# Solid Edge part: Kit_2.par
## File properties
Sűrűség: 0,000 kg/m^3
Pontosság: 0,990
Author: ahadarics
Last saved by: psaghy
Revision: 77
Username: ahadarics
Dokumentum tartalom típus: 0
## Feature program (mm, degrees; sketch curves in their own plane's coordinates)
base feature "unnamed BaseFeature 1"
sketch for "Furat_1" plane through (0, 0, -117) normal (0, 0, -1) x-axis (0, 1, 0)
  hole centre (-23.25, 23.25) bore radius 3.3235
hole "Furat_1" nominal diameter 8 finite  VBottomAngle = 118 deg; ThreadDepth = 16 mm
sketch for "unnamed Hole 1" plane through (0, 0, -117) normal (0, 0, -1) x-axis (0, 1, 0)
  hole centre (-23.25, -23.25) bore radius 3.3235
hole "unnamed Hole 1" finite
sketch for "unnamed Hole 2" plane through (0, 0, -117) normal (0, 0, -1) x-axis (0, 1, 0)
  hole centre (23.25, -23.25) bore radius 3.3235
hole "unnamed Hole 2" finite
sketch for "unnamed Hole 3" plane through (0, 0, -117) normal (0, 0, -1) x-axis (0, 1, 0)
  hole centre (23.25, 23.25) bore radius 3.3235
hole "unnamed Hole 3" finite
pattern "unnamed Pattern 1" of "Furat_1", "unnamed Hole 1", "unnamed Hole 2", "unnamed Hole 3"
sketch for "Furat_5" plane through (32.5, -0.007, -99.2488) normal (1, 0, 0) x-axis (0, 0, -1)
hole "Furat_5" diameter 13.157 finite  ThreadDepth = 10 mm
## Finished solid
Body 1: solid body, 381 faces, 916 edges, 586 vertices, 4 internal voids.
  Faces by surface: plane 155, cylinder 116, torus 41, cone 34, spline 19, swept 9, sphere 7
  Edges by curve: line 399, circle 264, curve on surface 230, spline 23
Bounding box of the edges (mm; curved faces can reach further): 65.001 x 65.000 x 35.000, from (-32.5, -32.5, -121) to (32.5008, 32.5, -86).
Cylindrical faces by radius (mm): R0.3125 x1, R0.3838 x1, R0.4089 x1, R0.4253 x1, R0.4408 x1, R0.5 x7, R0.5003 x1, R0.5483 x1, R0.5961 x1, R0.615 x1, R0.6311 x1, R0.6362 x1, R0.652 x1, R0.6792 x1, R0.73 x1, R0.7378 x1, R0.9114 x1, R0.9398 x1, R1 x12, R1.0011 x6, R1.0026 x1, R1.0394 x1, R1.0539 x1, R1.0734 x1, R1.0987 x1, R1.1871 x1, R1.2561 x1, R1.2722 x2, R1.3621 x1, R1.3711 x1, R1.5 x3, R1.7143 x1, R1.75 x3, R3 x3, R3.3235 x8, R4 x4, R4.15 x4, R4.95 x1, R5 x2, R5.7225 x1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
Conical faces (half-angle, radius in mm at the cone's reference point): 30 deg R5.1443 x1, 31.4296 deg R28.625 x4, 45 deg R2.25 x3, 45 deg R2.5 x3, 45 deg R2.75 x1, 45 deg R2.825 x1, 45 deg R4.3 x8, 45 deg R6.35 x8, 45 deg R6.72 x1, 59 deg R3.3235 x4
Toroidal faces (ring radius, tube radius in mm): R0.4909 r0.5044 x1, R0.5093 r0.5005 x1, R0.8674 r0.5067 x1, R1.4977 r0.5004 x6, R1.6 r0.1 x3, R4.3 r0.3 x4, R4.7 r0.3 x1, R6.45 r0.2 x4, R7.15 r0.5 x4, R9.5 r0.5 x1, R9.75 r0.5 x2, R13.9897 r0.5062 x1, R19.5 r0.5 x1, R20.5 r0.5 x1, R27.25 r1 x3, R31.75 r1 x6, R33.3108 r1 x1
Spherical faces by radius (mm): R0.5 x1, R1 x6
Planar faces by outward normal: +x 26, +y 8, +z 17, -x 8, -y 8, -z 34, oblique 54
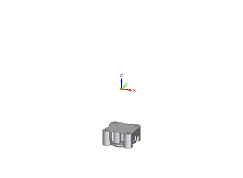
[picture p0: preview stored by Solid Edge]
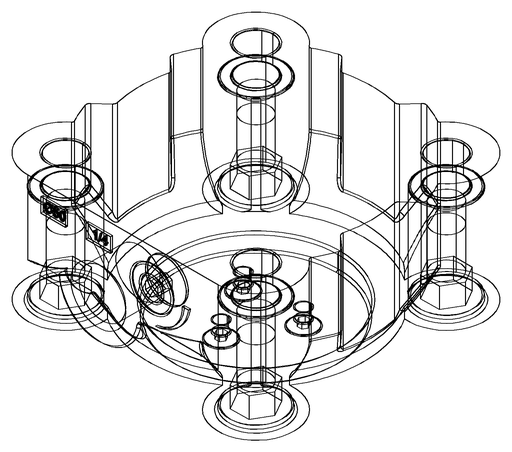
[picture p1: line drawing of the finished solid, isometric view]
